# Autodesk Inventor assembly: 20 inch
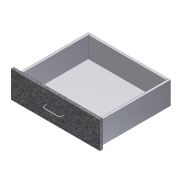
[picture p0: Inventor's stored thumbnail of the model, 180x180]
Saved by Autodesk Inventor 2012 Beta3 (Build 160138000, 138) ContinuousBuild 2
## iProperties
Created: 2011-02
Part Number: 20 inch
Document SubType Name: Assembly
Designer: Beta-8540w
Author: Beta-8540w
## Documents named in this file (12)
- C:\Inventor 2012 Essentials\Assemblies\Chapter 15\c15-04\c15-04-02.iam
- C:\Inventor 2012 Essentials\Parts\Chapter 15\c15-11.ipt
- C:\Inventor 2012 Essentials\Parts\Chapter 15\c15-12.ipt
- C:\Inventor 2012 Essentials\Parts\Chapter 15\c15-13.ipt
- C:\Inventor 2012 Essentials\Parts\Chapter 15\c15-15.ipt
- C:\Inventor 2012 Essentials\Parts\Chapter 15\c15-16.ipt
- C:\Inventor 2012 Essentials\Content Center Files\en-US\ANSI B18.6.3(28)\ANSI B18.6.3 - 8-36 UNF - 0.875(12).ipt
- C:\Inventor 2012 Essentials\Assemblies\Chapter 15\c15-04.iam
- C:\Inventor 2012 Essentials\Parts\Chapter 15\c15-11\c15-11-02.ipt
- C:\Inventor 2012 Essentials\Parts\Chapter 15\c15-12\c15-12-02.ipt
- C:\Inventor 2012 Essentials\Parts\Chapter 15\c15-13\c15-13-02.ipt
- C:\Inventor 2012 Essentials\Parts\Chapter 15\c15-15\c15-15-02.ipt
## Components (8 placed, 6 different names)
1. c15-11-02:1 — Mate:1, Flush:1, Mate:2, Mate:6, Mate:7, Wire Pull Insert 1, Wire Pull Insert 2, Wire Pull Screw constraint 1, Wire Pull Screw constraint 2, Mate:10, Mate:11
2. c15-12-02:1 — Flush:2, Mate:9, Flush:4, Flush:5, Flush:6
3. c15-13-02:1 — Mate:1, Flush:1, Mate:2, Flush:2, Mate:8, Mate:9, Flush:4, Flush:5
4. c15-13-02:2 — Flush:6, Mate:10, Mate:11
5. c15-15-02:1 — Mate:6, Mate:7, Mate:8
6. c15-16:1 — Wire Pull Insert 1, Wire Pull Insert 2
7. Cross Recessed Truss Head Machine Screw - Type IA - Inch No. 8 - 36 - 7/8:1 — Wire Pull Screw constraint 1
8. Cross Recessed Truss Head Machine Screw - Type IA - Inch No. 8 - 36 - 7/8:2 — Wire Pull Screw constraint 2
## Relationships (17: Mate 8, Flush 5, Insert 4)
- Mate:1: c15-11-02:1 ↔ c15-13-02:1
- Flush:1: c15-11-02:1 ↔ c15-13-02:1
- Mate:2: c15-11-02:1 ↔ c15-13-02:1
- Flush:2: c15-12-02:1 ↔ c15-13-02:1
- Mate:6: c15-11-02:1 ↔ c15-15-02:1
- Mate:7: c15-11-02:1 ↔ c15-15-02:1
- Mate:8: c15-13-02:1 ↔ c15-15-02:1
- Mate:9: c15-12-02:1 ↔ c15-13-02:1
- Flush:4: c15-12-02:1 ↔ c15-13-02:1
- Flush:5: c15-12-02:1 ↔ c15-13-02:1
- Wire Pull Insert 1 [Insert]: c15-11-02:1 ↔ c15-16:1
- Wire Pull Insert 2 [Insert]: c15-11-02:1 ↔ c15-16:1
- Wire Pull Screw constraint 1 [Insert]: c15-11-02:1 ↔ Cross Recessed Truss Head Machine Screw - Type IA - Inch No. 8 - 36 - 7/8:1
- Wire Pull Screw constraint 2 [Insert]: c15-11-02:1 ↔ Cross Recessed Truss Head Machine Screw - Type IA - Inch No. 8 - 36 - 7/8:2
- Flush:6: c15-12-02:1 ↔ c15-13-02:2
- Mate:10: c15-11-02:1 ↔ c15-13-02:2
- Mate:11: c15-11-02:1 ↔ c15-13-02:2
